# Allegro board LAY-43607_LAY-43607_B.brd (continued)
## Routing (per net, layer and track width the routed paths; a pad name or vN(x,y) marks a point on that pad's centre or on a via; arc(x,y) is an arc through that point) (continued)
D1_MECC0: length 49
  TOP w0.137: v3(67.03,35.8) 67.02,35.8 U14.M26 ; U565.G2 v2(67.08,13.71)
  L4_INT_2 w0.107: v3(67.03,35.8) 67.03,35.54 66.6,35.11 66.6,34.61 66.7,34.51 67.19,34.51 67.32,34.38 67.32,34.21 67.19,34.08 66.7,34.08 66.6,33.97 66.6,32.64 70.04,29.2 70.04,26.28 71.98,24.35 73.4,24.35 73.72,24.03 73.72,23.51 73.55,23.34 72.52,23.34 72.37,23.19 72.37,23.02 72.48,22.92 73.55,22.92 73.68,22.79 73.68,22.62 73.55,22.49 72.53,22.49 72.37,22.33 72.37,22.16 72.48,22.06 73.55,22.06 73.67,21.93 73.67,21.75 73.55,21.63 72.52,21.63 72.37,21.48 72.37,21.31 72.48,21.2 73.55,21.2 73.65,21.1 73.65,20.94 73.55,20.84 72.5,20.84 72.35,20.69 72.35,20.52 72.45,20.41 73.48,20.41 73.72,20.18 73.72,19.94 73.61,19.84 72.9,19.84 72.79,19.73 72.79,19.52 72.9,19.41 73.61,19.41 73.72,19.3 73.72,18.87 73.93,18.66 73.93,14.92 73.82,14.82 73.48,14.82 73.38,14.71 73.38,14.5 73.48,14.39 73.82,14.39 73.93,14.28 73.93,12.74 73.67,12.48 73.37,12.48 73.1,12.75 73.1,13.11 72.92,13.29 71.59,13.29 70.91,13.98 67.35,13.98 v2(67.08,13.71)
D1_MECC1: length 49.1
  TOP w0.137: U14.N25 66.22,36.6 v3(66.23,36.6) ; U565.F7 v2(71.88,14.51)
  L4_INT_2 w0.107: v3(66.23,36.6) 66.55,36.6 66.66,36.49 66.66,35.58 66.18,35.1 66.18,32.47 69.63,29.03 69.63,28.63 69.52,28.52 69.34,28.52 69.23,28.42 69.23,28.2 69.34,28.1 69.52,28.1 69.63,27.99 69.63,27.78 69.52,27.67 69.36,27.67 69.26,27.56 69.26,27.35 69.36,27.24 69.52,27.24 69.63,27.14 69.63,26.92 69.52,26.82 69.36,26.82 69.26,26.71 69.26,26.5 69.36,26.39 69.52,26.39 69.63,26.28 69.63,26.09 69.63,25.88 69.99,25.52 69.99,25.37 69.5,24.88 69.5,24.61 69.59,24.52 69.74,24.52 70.39,25.17 70.54,25.17 70.69,25.02 70.69,24.87 70.05,24.23 70.05,24.08 70.2,23.93 70.35,23.93 71,24.57 71.14,24.57 71.28,24.43 71.28,24.28 70.73,23.74 70.73,23.59 70.89,23.44 71.04,23.44 71.57,23.97 71.74,23.97 72.08,23.63 72.08,23.48 71.71,23.11 70.89,23.11 70.78,23 70.78,22.81 70.89,22.71 71.79,22.71 71.92,22.58 71.92,22.39 71.81,22.28 70.89,22.28 70.78,22.17 70.78,21.96 70.89,21.85 71.79,21.85 71.92,21.72 71.92,21.53 71.81,21.43 70.89,21.43 70.78,21.32 70.78,21.11 70.89,21 71.79,21 71.92,20.87 71.92,20.67 71.81,20.56 70.89,20.56 70.78,20.46 70.78,20.24 70.89,20.14 71.8,20.14 71.92,20.02 71.92,19.81 73.1,18.63 73.1,18.11 72.99,18 71.69,18 71.58,17.89 71.58,17.68 71.69,17.57 72.97,17.57 73.1,17.44 73.1,17.25 72.99,17.15 71.69,17.15 71.58,17.04 71.58,16.83 71.69,16.72 72.97,16.72 73.1,16.59 73.1,14.35 72.84,14.09 72.3,14.09 v2(71.88,14.51)
D1_MECC2: length 49.1
  TOP w0.137: v3(63.03,36.59) 63.03,36.6 U14.T25 ; v2(68.97,12.08) 68.54,12.51 U565.H3
  L4_INT_2 w0.107: v2(68.97,12.08) 68.97,12.34 68.76,12.55 68.06,12.55 67.95,12.45 67.95,12.04 67.84,11.94 67.63,11.94 67.52,12.04 67.52,12.25 67.42,12.35 67.2,12.35 67.1,12.25 67.1,12.04 66.99,11.94 66.78,11.94 66.67,12.04 66.67,12.42 66.56,12.52 65.9,12.52 65.51,12.13 65.17,12.13 64.93,12.37 64.93,12.53 65.12,12.72 65.51,12.72 65.72,12.93 65.72,13.28 65.61,13.39 65.28,13.39 65.13,13.54 65.13,13.78 65.24,13.89 65.43,13.89 65.55,14.01 65.55,14.69 65.45,14.8 65.02,14.8 64.91,14.91 64.91,15.12 65.02,15.23 65.45,15.23 65.55,15.33 65.55,15.57 65.4,15.72 65.16,15.72 64.97,15.92 64.97,16.75 65.08,16.85 65.57,16.85 65.68,16.96 65.68,17.17 65.57,17.28 65.02,17.28 64.91,17.39 64.91,17.62 65,17.71 65.57,17.71 65.68,17.81 65.68,18.03 65.57,18.13 65.08,18.13 64.97,18.24 64.97,18.62 64.76,18.83 64.76,18.98 65.17,19.39 65.17,19.54 65.01,19.69 64.86,19.69 64.45,19.28 64.3,19.28 64.14,19.45 64.14,24.77 63.96,24.96 63.96,25.11 64.34,25.49 64.34,25.77 64.22,25.89 64.01,25.89 63.59,25.47 63.44,25.47 63.33,25.58 63.33,25.73 63.79,26.18 63.79,26.33 63.64,26.49 63.4,26.49 62.99,26.07 62.84,26.07 62.36,26.55 62.36,27.03 62.46,27.14 63.05,27.14 63.15,27.25 63.15,27.46 63.05,27.57 62.5,27.57 62.36,27.7 62.36,27.89 62.46,27.99 63.05,27.99 63.15,28.1 63.15,28.31 63.05,28.42 62.5,28.42 62.36,28.56 62.36,28.74 62.46,28.85 63.05,28.85 63.15,28.95 63.15,29.17 63.05,29.27 62.5,29.27 62.36,29.41 62.36,30.8 62.48,30.92 62.86,30.92 62.97,31.02 62.97,31.24 62.86,31.34 62.46,31.34 62.36,31.45 62.36,31.65 62.48,31.77 62.76,31.77 62.86,31.88 62.86,32.08 62.76,32.18 62.46,32.18 62.36,32.29 62.36,33.02 62.7,33.36 62.7,33.88 62.52,34.06 62.19,34.06 62.08,34.16 62.08,34.38 62.19,34.48 62.52,34.48 62.63,34.59 62.63,36.2 v3(63.03,36.59)
D1_MECC3: length 49
  TOP w0.137: U565.H7 v2(71.88,12.91) ; v3(63.03,37.39) 63.03,37.4 U14.T24
  L4_INT_2 w0.107: v3(63.03,37.39) 62.63,37 61.92,37 61.81,36.89 61.81,32.78 61.95,32.64 61.95,26.29 63.7,24.53 63.7,24.38 63.71,24.38 63.71,18.75 63.81,18.65 64.36,18.65 64.55,18.46 64.55,18.33 64.44,18.22 63.81,18.22 63.71,18.11 63.71,17.9 63.81,17.79 64.43,17.79 64.5,17.72 64.5,17.42 64.44,17.37 63.81,17.37 63.71,17.26 63.71,17.05 63.81,16.94 64.43,16.94 64.55,16.82 64.55,16.62 64.44,16.51 63.81,16.51 63.71,16.41 63.71,16.12 63.81,16.01 64.39,16.01 64.5,15.9 64.5,14.52 64.24,14.26 64.24,13.12 62.85,11.73 62.85,11.58 63.05,11.37 63.16,11.37 63.78,11.99 63.79,11.99 64.16,12.36 64.36,12.36 65,11.72 66.07,11.72 66.16,11.63 69.46,11.63 69.57,11.74 69.57,12.79 69.68,12.9 69.97,12.9 70.07,12.79 70.07,11.78 70.23,11.63 70.47,11.63 70.58,11.74 70.58,12.04 70.68,12.15 70.9,12.15 71,12.04 71,11.87 71.11,11.77 71.74,11.77 72.03,12.06 72.5,12.06 72.64,12.2 72.64,12.35 72.09,12.91 v2(71.88,12.91)
D1_MECC4: length 49.1
  TOP w0.137: U14.M25 67.02,36.6 v3(67.03,36.6) ; U565.H2 67.08,12.11 66.12,12.11 66.04,12.03 65.44,12.03 65.3,12.16 65.3,13.48 65.12,13.66 64.52,13.66 64.38,13.53 64.38,12.57 64.25,12.43 64.05,12.43 v2(63.29,13.19)
  L4_INT_2 w0.107: v2(63.29,13.19) 63.29,12.77 63.05,12.53 62.9,12.53 62.79,12.64 62.79,13.56 62.9,13.66 63.71,13.66 63.83,13.78 63.83,14.01 63.71,14.13 62.86,14.13 62.7,14.29 62.7,14.45 62.81,14.56 63.59,14.56 63.73,14.69 63.73,14.84 63.59,14.98 62.86,14.98 62.7,15.14 62.7,15.31 62.85,15.46 63.19,15.46 63.29,15.57 63.29,24.21 63.29,24.21 63.29,24.36 61.53,26.12 61.53,32.47 61.38,32.62 61.38,33.97 61.27,34.08 60.61,34.08 60.51,34.19 60.51,34.4 60.61,34.51 61.27,34.51 61.38,34.61 61.38,35.22 61.03,35.57 61.03,37.55 61.27,37.8 64.47,37.8 64.58,37.69 64.58,36.83 64.69,36.72 64.9,36.72 65.01,36.83 65.01,37.69 65.11,37.8 65.59,37.8 65.83,37.56 65.83,37.26 66.09,37 66.92,37 67.03,36.89 v3(67.03,36.6)
D1_MECC5: length 49.1
  TOP w0.137: v3(66.23,37.4) 65.83,37.8 U14.N24 ; U565.H8 v2(72.68,12.91)
  L4_INT_2 w0.107: v3(66.23,37.4) 66.23,37.47 65.81,37.89 65.81,38.36 66.04,38.59 67.17,38.59 67.44,38.32 67.44,35.64 67.63,35.45 67.63,33.87 67.52,33.76 67.05,33.76 66.94,33.66 66.94,33.44 67.05,33.34 67.52,33.34 67.63,33.23 67.63,32.25 67.68,32.21 67.68,32.2 70.55,29.33 70.55,29.32 70.79,29.08 70.79,28.71 70.68,28.6 70.56,28.6 70.45,28.49 70.45,28.28 70.56,28.17 70.68,28.17 70.79,28.07 70.79,27.85 70.68,27.75 70.56,27.75 70.45,27.64 70.45,27.43 70.56,27.32 70.68,27.32 70.79,27.21 70.79,26.11 72.15,24.76 72.4,24.76 72.51,24.86 72.51,24.92 72.62,25.03 72.83,25.03 72.94,24.92 72.94,24.86 73.04,24.76 73.59,24.76 74.13,24.22 74.13,23.56 74.25,23.43 74.97,23.43 75.11,23.29 75.11,23.14 74.97,23.01 74.25,23.01 74.13,22.88 74.13,22.7 74.28,22.55 75.75,22.55 75.88,22.42 75.88,22.25 75.74,22.12 74.23,22.12 74.13,22.01 74.13,21.85 74.25,21.73 75.37,21.73 75.5,21.59 75.5,21.44 75.37,21.3 74.25,21.3 74.13,21.17 74.13,21 74.25,20.87 75.27,20.87 75.4,20.75 75.4,20.58 75.27,20.44 74.25,20.44 74.13,20.32 74.13,20.14 74.25,20.02 74.99,20.02 75.12,19.89 75.12,19.72 74.99,19.59 74.47,19.59 74.36,19.48 74.36,12.5 74.05,12.18 73.12,12.18 72.68,12.63 v2(72.68,12.91)
D1_MECC6: length 49
  TOP w0.137: v3(63.82,36.59) 63.82,36.6 U14.R25 ; U565.J3 68.33,11.66 69.15,11.66 69.41,11.91 69.41,12.3 70.9,13.78 70.9,14.7 70.42,15.17 70.42,15.77 70.28,15.91 70.09,15.91 69.95,15.77 69.95,15.09 70.44,14.6 70.44,13.78 69.83,13.17 v2(69.41,13.17)
  L4_INT_2 w0.107: v3(63.82,36.59) 63.82,36.92 63.72,37.03 63.52,37.03 63.38,36.89 63.38,35.98 63.41,35.96 63.41,35.64 63.06,35.29 63.06,35.1 63.17,34.99 63.94,34.99 64.05,34.89 64.05,34.67 63.94,34.57 63.21,34.57 63.1,34.46 63.1,34.25 63.21,34.14 63.81,34.14 63.95,33.99 63.95,33.84 63.79,33.68 63.17,33.68 63.06,33.56 63.06,32.46 63.38,32.14 63.38,30.85 63.23,30.71 63.23,29.83 63.56,29.5 63.56,27.14 64.94,25.77 64.94,24.77 64.55,24.38 64.55,24.2 64.66,24.09 65.15,24.09 65.26,23.98 65.26,23.77 65.15,23.66 64.66,23.66 64.55,23.56 64.55,23.34 64.66,23.24 65.15,23.24 65.26,23.13 65.26,22.92 65.15,22.81 64.66,22.81 64.55,22.7 64.55,22.49 64.66,22.38 65.15,22.38 65.26,22.28 65.26,22.06 65.15,21.96 64.66,21.96 64.55,21.85 64.55,21.64 64.66,21.53 65.15,21.53 65.26,21.42 65.26,21.21 65.15,21.1 64.66,21.1 64.55,21 64.55,20.51 64.95,20.1 65.29,20.1 66,19.39 66,18.89 65.9,18.78 65.9,13.52 66.12,13.29 66.44,13.29 66.76,12.97 67.71,12.97 67.82,13.08 67.82,13.2 67.95,13.33 68.14,13.33 68.25,13.22 68.25,13 68.35,12.9 69.14,12.9 v2(69.41,13.17)
D1_MECC7: length 49
  TOP w0.137: U565.J7 v2(70.65,12.53) ; v3(63.82,37.39) 63.82,37.4 U14.R24
  L4_INT_2 w0.107: v2(70.65,12.53) 71.15,12.53 71.47,12.21 71.83,12.21 71.91,12.29 71.91,12.44 71.82,12.52 71.72,12.52 71.5,12.75 71.5,12.85 71.28,13.07 71.2,13.07 70.69,13.58 67.73,13.58 67.47,13.32 66.92,13.32 66.66,13.58 66.66,15.08 66.77,15.19 67.13,15.19 67.24,15.3 67.24,15.51 67.13,15.62 66.77,15.62 66.66,15.72 66.66,16.68 66.77,16.78 67.34,16.78 67.44,16.89 67.44,17.1 67.34,17.21 66.78,17.21 66.66,17.32 66.66,19.51 65.67,20.5 65.67,26.21 65.55,26.33 64.95,26.33 64.82,26.47 64.82,26.61 64.92,26.72 65.54,26.72 65.62,26.79 65.62,27 65.48,27.14 64.15,27.14 64.02,27.27 64.02,27.46 64.12,27.57 65.51,27.57 65.62,27.67 65.62,27.88 65.51,27.98 64.08,27.98 63.98,28.09 63.98,28.3 64.08,28.41 65.51,28.41 65.62,28.52 65.62,28.83 65.09,29.35 64.83,29.35 64.29,28.81 64.14,28.81 63.98,28.96 63.98,29.11 64.55,29.68 64.55,30.13 64.44,30.23 63.75,30.23 63.65,30.34 63.65,30.53 63.77,30.66 64.24,30.66 64.39,30.82 64.39,31.05 64.24,31.2 63.9,31.2 63.8,31.3 63.8,31.52 63.9,31.62 64.24,31.62 64.35,31.73 64.35,32.05 64.05,32.34 64.05,32.61 63.91,32.75 63.58,32.75 63.47,32.86 63.47,33.06 63.59,33.18 63.95,33.18 64.05,33.28 64.05,33.48 64.19,33.62 64.2,33.62 64.3,33.73 64.3,37.29 64.2,37.39 v3(63.82,37.39)
D1_MODT0: length 142.7
  TOP w0.137: v1(79.76,10.91) 79.36,11.31 78,11.31 77.38,10.7 77.19,10.7 77.04,10.85 76.44,10.85 76.18,11.11 76.18,11.96 76.04,12.1 75.42,12.1 75.3,11.98 75.3,11.33 75.18,11.21 75.01,11.21 74.89,11.33 74.89,11.98 74.77,12.1 74.6,12.1 74.48,11.98 74.48,11.33 74.36,11.21 74.19,11.21 74.07,11.33 74.07,11.98 73.95,12.1 73.68,12.1 73.54,11.96 73.54,11.44 73.41,11.31 70.48,11.31 70.35,11.44 70.35,12.01 70.21,12.14 69.93,12.14 69.8,12.01 69.8,11.44 69.66,11.31 68.68,11.31 v1(68.28,10.91) ; v2(90.08,20.85) 90.1,20.83 94.68,20.83 94.82,20.97 94.82,21.19 94.68,21.33 65.01,21.33 56.38,29.95 56.38,33.58 57.02,34.22 U14.AD28 ; v1(45.32,10.91) 44.92,11.31 44.92,11.9 44.72,12.11 44.31,12.11 44.12,12.29 44.12,12.75 43.96,12.91 43.47,12.91 43.34,13.05 43.34,13.13 43.32,13.14 43.32,14.74 42.92,15.14 42.92,15.57 42.81,15.68 42.46,15.68 42.21,15.93 42.21,16.51 41,17.72 R135.1
  L3_INT_1 w0.107: v1(45.32,10.91) 45.32,13.84 46.14,14.66 47.71,14.66 47.91,14.86 48.74,14.86 48.76,14.89 49.08,14.89 49.11,14.86 49.54,14.86 49.56,14.89 49.88,14.89 49.91,14.86 51.49,14.86 52.82,13.53 53.41,13.53 53.65,13.29 56.6,13.29 56.8,13.09 v1(56.8,10.91) 57.07,10.91 57.4,11.24 57.4,11.91 58.01,12.52 58.36,12.52 58.78,12.94 58.78,14.54 59.13,14.89 63.68,14.89 63.84,14.74 65.44,14.74 65.9,14.28 65.9,13.55 66.12,13.32 67.75,13.32 68.28,12.8 v1(68.28,10.91) ; v2(90.08,20.85) 89.64,20.41 89.64,14.29 90.44,13.49 90.44,12.5 90.41,12.46 90.41,11.74 91.24,10.91 v1(91.24,10.91)
  L4_INT_2 w0.107: v1(91.24,10.91) 91.24,11.29 90.81,11.72 90.68,11.72 90.3,12.11 89.53,12.11 89.43,12.21 89.43,12.42 89.32,12.52 89.11,12.52 89,12.42 89,12.21 88.89,12.11 88.32,12.11 88.32,12.11 85.57,12.11 85.43,12.25 83.26,12.25 82.32,11.31 81.4,11.31 81.29,11.2 81.29,10.85 81.19,10.75 80.97,10.75 80.87,10.85 80.87,11.42 80.69,11.6 79.55,11.6 79.38,11.42 79.38,11.1 79.56,10.91 v1(79.76,10.91)
D1_MRAS_B: length 139.7
  TOP w0.137: v1(83.76,10.11) 83.76,10.28 84.16,10.68 84.16,11.07 84.4,11.31 84.73,11.31 84.96,11.54 84.96,12.29 85.23,12.57 85.58,12.57 85.71,12.7 85.71,13.57 85.85,13.71 86.13,13.71 86.26,13.57 86.26,12.7 86.4,12.57 88.81,12.57 89.24,12.14 89.24,11.54 89.48,11.31 92.05,11.31 92.19,11.45 92.19,11.5 92.33,11.64 92.6,11.64 92.74,11.5 92.74,11.45 92.88,11.31 95.51,11.31 95.64,11.17 95.64,10.51 v1(95.24,10.11) ; R127.1 45.81,5.35 45.81,9.81 45.92,9.92 46.38,9.92 46.57,10.12 46.57,10.57 46.8,10.8 48.07,10.8 48.36,10.51 48.92,10.51 v1(49.32,10.11) ; U14.AA28 59.42,33.81 59.34,33.73 59.34,29.5 65.74,23.1 84.05,23.1 84.59,23.64 94.98,23.64 96.52,22.1 v2(96.52,21.25)
  L3_INT_1 w0.107: v1(95.24,10.11) 95.62,10.49 95.62,11.07 95.88,11.32 96.26,11.32 97.08,12.15 97.08,14.18 97.24,14.33 97.72,14.33 97.88,14.49 97.88,14.71 97.72,14.87 97.24,14.87 97.08,15.02 97.08,16.24 97.24,16.4 97.62,16.4 97.77,16.55 97.77,16.77 97.62,16.93 97.24,16.93 97.08,17.09 97.08,17.31 97.24,17.46 97.62,17.46 97.77,17.62 97.77,17.84 97.62,18 97.24,18 97.08,18.15 97.08,18.47 95.99,19.56 95.99,20.72 v2(96.52,21.25) ; v1(60.8,10.11) 60.38,10.52 59.84,10.52 59.83,10.53 57.95,10.53 57.11,9.69 55.04,9.69 54.69,9.34 52.69,9.34 52.39,9.64 52.39,12.34 52.22,12.5 49.23,12.5 48.93,12.2 48.93,10.5 v1(49.32,10.11)
  BOTTOM w0.137: v1(83.76,10.11) 83.49,9.84 82.63,9.84 82.46,9.67 82.18,9.67 81.91,9.94 81.91,10.72 81.14,11.48 78.12,11.48 77.79,11.16 77.79,11.1 77.76,11.07 77.76,10.23 77.42,9.89 75.16,9.89 75.02,10.02 75.02,10.26 74.88,10.39 74.61,10.39 74.47,10.26 74.47,10.02 74.34,9.89 73.88,9.89 73.35,10.42 73.34,10.42 73.25,10.51 72.68,10.51 v1(72.28,10.11) 71.72,10.11 71.3,9.69 70.21,9.69 70.07,9.83 70.07,10.35 69.93,10.48 69.66,10.48 69.52,10.35 69.52,9.83 69.38,9.69 68.46,9.69 68.45,9.71 66.46,9.71 65.82,10.34 63.22,10.34 62.98,10.11 62.98,9.3 62.59,8.91 61.34,8.91 61.2,9.04 61.2,9.71 v1(60.8,10.11)
D1_MWE_B: length 134.2
  TOP w0.137: U14.AB28 58.62,34.22 58.41,34.01 58.41,33.03 58.57,32.87 58.74,32.87 58.9,32.71 58.9,32.48 58.74,32.32 58.57,32.32 58.41,32.16 58.41,31.93 58.57,31.77 58.74,31.77 58.9,31.61 58.9,31.39 58.74,31.22 58.57,31.22 58.41,31.06 58.41,29.8 65.56,22.65 85.18,22.65 v2(85.35,22.83) ; v1(44.52,10.11) 44.34,10.11 43.94,10.51 43.54,10.51 42,12.06 42,14.27 41.78,14.49 41.61,14.49 41.38,14.26 41.21,14.26 41.09,14.38 41.09,14.55 41.22,14.68 41.22,14.88 41.09,15.01 R126.1
  L3_INT_1 w0.107: v1(90.44,10.11) 90.29,10.11 89.89,10.51 89.52,10.51 89.5,10.52 89.48,10.52 88.99,11.02 88.99,11.51 89.04,11.57 89.04,11.97 88.48,12.53 88.48,12.95 87.91,13.52 87.45,13.52 87.16,13.81 87.16,19.74 83.26,23.64 83.26,24.01 81.1,26.16 81.1,26.31 81.41,26.62 81.56,26.62 v2(85.35,22.83)
  L4_INT_2 w0.107: v1(44.52,10.11) 44.94,9.69 46.71,9.69 46.87,9.54 46.87,9.16 47.26,8.77 47.26,8.53 47.37,8.43 47.74,8.43 47.83,8.51 47.83,9.16 48.36,9.69 50.28,9.69 50.77,9.2 50.77,8.71 50.94,8.55 51.68,8.55 51.89,8.75 51.89,9.36 52.69,10.16 54.71,10.16 55.04,10.49 55.36,10.49 55.58,10.27 55.58,10.06 55.69,9.95 55.84,9.95 v1(56,10.11) 56.16,10.11 56.58,9.69 57.38,9.69 57.9,9.17 57.9,8.14 58.04,8 58.67,8 58.79,8.11 58.79,9.44 59.84,10.49 62.5,10.49 63.24,9.75 63.88,9.75 64.3,10.18 65.75,10.18 66.07,10.49 67.1,10.49 v1(67.48,10.11) 67.86,10.49 68.44,10.49 68.58,10.36 70.56,10.36 70.69,10.49 72.12,10.49 72.12,10.49 72.44,10.49 72.44,10.49 72.7,10.23 72.7,9.95 72.92,9.72 73.24,9.72 73.32,9.81 73.72,9.81 73.83,9.91 73.83,10.54 73.94,10.64 74.15,10.64 74.26,10.54 74.26,9.91 74.36,9.81 74.58,9.81 74.68,9.91 74.68,10.54 74.79,10.64 75,10.64 75.11,10.54 75.11,9.91 75.22,9.81 77.32,9.81 78,10.49 78.58,10.49 v1(78.96,10.11)
  BOTTOM w0.137: v1(90.44,10.11) 90.16,10.11 90.03,9.97 90.03,9.85 89.89,9.71 89.1,9.71 88.75,10.06 88.58,10.06 88.53,10.11 87.05,10.11 87.01,10.06 86.04,10.06 84.88,8.91 82.8,8.91 82.39,9.32 81.11,9.32 80.74,9.69 80.74,9.89 81.37,10.51 81.37,10.71 81.17,10.9 80.98,10.9 80.35,10.28 80.16,10.28 79.93,10.51 79.36,10.51 v1(78.96,10.11)
D1_PAROUT: length 135.9
  TOP w0.137: U565.T3 68.28,6.11 v2(68.69,5.69) ; v2(72.81,25.44) 71.66,25.44 71.66,25.45 66.51,25.45 62.2,29.76 62.2,32.87 62.73,33.41 62.73,33.69 U14.V28 ; U17.T3 57.01,5.71 57.01,5.66 57.08,5.59 v2(57.08,5.53) ; R134.1 40.13,5.57 40.34,5.36 40.34,5.16 40.1,4.92 40.1,4.72 40.29,4.53 40.49,4.53 40.73,4.77 40.93,4.77 41.31,4.39 42.35,4.39 42.48,4.53 44.09,4.53 44.1,4.54 44.3,4.54 45.32,5.56 v1(45.32,6.11) ; v2(80.17,5.69) 80.17,5.7 U16.T3
  L3_INT_1 w0.107: v2(72.81,25.44) 71.84,25.44 71.73,25.55 71.73,26.37 71.63,26.48 69.55,26.48 69.44,26.37 69.44,20.77 70.07,20.15 79.38,20.15 81.17,18.35 81.17,17.91 80.87,17.61 80.87,16.93 80.33,16.4 80.33,15.49 80.85,14.97 80.85,14.36 80.43,13.93 80.43,12.81 81.44,11.79 81.44,8.68 82.8,7.32 83.12,7.32 83.18,7.38 85.13,7.38 86.05,6.45 86.67,6.45 87.73,5.39 89.24,5.39 89.95,6.11 v1(91.24,6.11) ; v2(80.17,5.69) 81.16,5.69 81.27,5.58 81.27,3.72 81.16,3.62 71.9,3.62 71.56,3.96 70.42,3.96 v2(68.69,5.69) 68.69,5.2 68.94,4.96 68.94,4.29 68.78,4.13 68.36,4.13 68.2,4.29 68.2,4.84 67.64,5.41 67.33,5.41 67.33,5.41 67.01,5.41 67.01,5.41 66.77,5.41 65.05,3.68 57.87,3.68 57.08,4.47 v2(57.08,5.53)
  L4_INT_2 w0.107: v1(45.32,6.11) 45.32,4.56 45.92,3.96 54.99,3.96 55.81,4.78 55.81,5.71 56.07,5.97 56.64,5.97 v2(57.08,5.53)
  BOTTOM w0.137: v2(80.17,5.69) 80.23,5.69 82.26,3.66 90.74,3.66 91.97,4.89 91.97,5.38 v1(91.24,6.11)
DDR4_CLK_TERM: length 1.7
  BOTTOM w0.137: C431.2 44.57,3.7 R138.2 46.21,3.7 R137.2
DDR4_ZQ0: length 2.4
  TOP w0.137: R105.1 61.65,14.15 U17.F9
DDR4_ZQ1: length 2.2
  TOP w0.137: U18.F9 50.17,14.15 51.75,14.15 51.79,14.11 R106.1
DDR4_ZQ2: length 2.1
  TOP w0.137: U15.F9 96.45,14.11 96.46,14.11 97.57,14.11 R103.1
DDR4_ZQ3: length 2.2
  TOP w0.137: U16.F9 84.61,14.15 R104.1
DDR4_ZQ5: length 2.3
  TOP w0.137: U565.F9 R107.1
DDR_CLK_100MHZ_LVCMOS: length 85.6
  TOP w0.137: R782.2 33.5,67.36 34.5,68.36 35.06,68.36 38.14,65.28 38.14,64.4 38.8,63.73 38.8,58.95 v2(37.34,57.48) ; v3(68.62,40.6) U14.J20
  L3_INT_1 w0.107: v2(37.34,57.48) 40.37,54.45 40.37,42.43 39.61,41.67 39.65,41.63 39.65,37.85 39.38,37.58 39.38,34.82 40.33,33.88 40.33,31.78 44.16,27.96 66.58,27.96 68.21,29.58 68.21,40.18 v3(68.62,40.6)
DDR_VREF1: length 3.5
  BOTTOM w0.254: v1(89.64,9.31) 89.08,9.31 C1406.1
  BOTTOM w0.381: R960.2 87.26,8.55 R961.1 C1406.1
DDR_VREF2: length 2.9
  BOTTOM w0.254: C1430.1 78.14,9.29 v1(78.16,9.31)
  BOTTOM w0.381: R963.1 76.14,9.28 R962.2 76.99,9.28 C1430.1
DDR_VREF3: length 3.4
  BOTTOM w0.254: R954.2 R955.1 C669.1 54.84,9.67 v1(55.2,9.31)
DDR_VREF4: length 2.7
  BOTTOM w0.254: v1(43.72,9.31) 43.7,9.29 C1382.1
  BOTTOM w0.381: R956.2 41.87,9.28 R957.1 C1382.1
DDR_VREF5: length 3
  BOTTOM w0.254: v1(66.68,9.31) 66.22,9.31 66.2,9.29 C1577.1
  BOTTOM w0.381: R959.1 64.62,9.28 R958.2 65.54,9.28 C1577.1
DDR_VTT: length 2
  TOP w0.254: v4(76.06,73.75) 75.7,74.11 75.7,74.55 75.48,74.76 U561.30
  vias: v2(37.12,19.52) v2(37.12,18.86) v2(37.81,19.52) v2(37.81,18.86) v2(38.44,19.52) v2(38.44,18.89) v2(39.08,19.52) v2(39.1,18.89) v4(81.49,76.22) v4(81.52,75.51) v4(82.41,76.6) v4(82.41,75.89) v4(82.41,75.18) v4(82.41,74.47)
DIFF_SYSCLK_N: length 56.4
  TOP w0.124: U14.AB13 v1(58.22,47) ; U50.16 23.6,64.84 23.51,64.75 19.72,64.75 18.99,64.02 18.99,60.55 20.5,59.04 22.17,59.04 23.04,59.91 23.5,59.91 v2(23.62,59.8)
  BOTTOM w0.124: v1(58.22,47) 58.21,47.01 57.7,47.01 56.76,46.08 52.14,46.08 51.56,46.66 49.89,46.66 47.59,48.97 44.22,48.97 32.68,60.51 29.44,60.51 28.94,60.01 23.83,60.01 v2(23.62,59.8)
DIFF_SYSCLK_P: length 56.4
  TOP w0.124: v2(23.62,60.54) 23.31,60.23 22.9,60.23 22.04,59.36 20.63,59.36 19.31,60.69 19.31,63.89 19.85,64.43 23.51,64.43 23.6,64.34 U50.17
  TOP w0.137: U14.AA13 v1(59.03,46.99)
  BOTTOM w0.124: v1(59.03,47) 58.63,47.39 57.62,47.39 56.63,46.4 52.28,46.4 51.69,46.98 50.02,46.98 47.72,49.29 44.36,49.29 32.81,60.83 29.31,60.83 28.8,60.33 23.83,60.33 v2(23.62,60.54)
EMI2_MDC: length 29
  TOP w0.137: R870.2 47.19,58.31 47.08,58.21 v2(46.7,58.21) ; U123.C11 37.42,69.94 v2(36.85,69.37)
  BOTTOM w0.137: v2(36.85,69.37) 37.28,69.37 37.56,69.65 44.47,69.65 45.25,68.87 45.25,66.96 44.71,66.42 44.71,66.37 41.92,63.58 41.92,61.62 45.34,58.21 v2(46.7,58.21) 47.63,58.21 47.73,58.31 R870.2
EMI2_MDIO: length 37.9
  TOP w0.137: R871.1 49.77,59.33 49.91,59.19 v2(49.91,58.64) 53.56,54.98 53.56,54.86 U14.AH3 ; U123.D10 37.86,72.27 37.86,69.34 v2(37.22,68.7)
  BOTTOM w0.137: v2(37.22,68.7) 37.91,69.39 44.36,69.39 44.86,68.89 44.86,66.94 41.66,63.74 41.66,61.51 45.39,57.78 49.05,57.78 v2(49.91,58.64)
FA_VL: length 3.9
  TOP w0.137: U14.U5 v1(62.22,53.39)
  TOP w0.381: U14.AB21 v1(59.02,40.6)
  L3_INT_1 w0.488: J12.2 41.57,38.16 ; J12.2 41.57,36.74 ; J12.2 42.28,37.45
  BOTTOM w0.508: R102.1 v4(45.83,36.56)
FTM7_CH0: length 104.4
  TOP w0.137: U14.A19 76.87,41.8 77.24,42.17 82.65,42.17 84.24,40.58 85.56,40.58 85.87,40.89 91.52,40.89 v2(91.83,40.58) ; v2(86.17,113.1) 86.64,112.63 U548.5
  L3_INT_1 w0.107: v2(88.53,102.67) 88.53,94.91 87.11,93.49 87.11,90.21 86.29,89.4 86.29,84.57 87.34,83.52 89.06,83.52 94.76,77.82 v2(95.77,77.82)
  L4_INT_2 w0.107: v2(91.83,40.58) 91.33,41.08 91.33,43.61 92.96,45.23 92.96,55.02 92.45,55.53 92.45,57.65 92.38,57.72 92.38,58.41 92.65,58.69 92.65,60.37 91,62.02 91,65.08 94.13,68.21 94.13,76.18 v2(95.77,77.82)
  BOTTOM w0.137: v2(86.17,113.1) 86.67,113.6 88.45,113.6 88.85,113.2 88.85,106.11 88.53,105.79 v2(88.53,102.67)
FUSE_PWR_STATUS#: length 59.9
  TOP w0.137: v2(94.85,63.94) 94.22,64.57 94.22,65.3 94.11,65.41 U566.4
  L3_INT_1 w0.107: v2(94.85,63.94) 95.53,63.26 97.5,63.26 97.63,63.39 98.35,63.39 99.14,62.6 104.13,62.6 104.98,61.75 108.78,61.75 v2(108.94,61.59)
  L4_INT_2 w0.107: v2(113.16,100.3) 113.7,99.76 113.7,82.54 110.73,79.57 110.73,63.15 109.17,61.59 v2(108.94,61.59)
  BOTTOM w0.137: R948.2 113.98,100.3 v2(113.16,100.3)
GPIO3_02: length 93.2
  TOP w0.137: J67.6 19.49,106.7 19.1,106.31 19.1,106.29 18.81,106.01 v2(18.39,106.01) ; v2(59.82,55) U14.Y3
  L3_INT_1 w0.107: v2(58.27,61.54) 57.62,62.2 54.29,62.2 53.35,61.26 46.56,61.26 46.23,61.59 45.05,61.59 43.11,63.52 36.23,63.52 34.99,64.77 33.61,64.77 28.36,70.02 23.32,70.02 21.92,71.41 18.55,71.41 17.5,72.46 17.5,78.71 18.05,79.26 18.05,91.24 17.5,91.79 17.5,101.23 18.21,101.94 18.21,103.74 18.89,104.41 18.89,105.55 18.71,105.72 18.68,105.72 v2(18.39,106.01)
  L4_INT_2 w0.107: v2(59.82,55) 60.21,55.38 60.21,55.95 59.82,56.34 59.82,59.99 v2(58.27,61.54)
  BOTTOM w0.137: U543.4 17.95,107.67 18.44,107.18 18.44,106.49 18.39,106.43 v2(18.39,106.01)
GPIO3_03: length 95.4
  TOP w0.137: J67.10 20.03,102.62 v2(20.03,103.2) ; v2(59.82,54.2) U14.Y4
  L3_INT_1 w0.107: v2(60.36,61.32) 60.36,61.95 55.87,66.44 35.77,66.44 34.5,65.16 33.54,65.16 28.38,70.32 23.34,70.32 22.02,71.64 18.65,71.64 17.73,72.56 17.73,78.55 18.7,79.51 18.7,96.88 19.41,97.59 19.41,102.58 v2(20.03,103.2)
  L4_INT_2 w0.107: v2(60.36,61.32) 60.08,61.03 60.08,59.62 60.43,59.27 60.43,54.8 v2(59.82,54.2)
  BOTTOM w0.137: v2(20.03,103.2) 19.26,102.43 19.26,100.29 17.99,99.01 U544.1
GPIO3_04: length 99.9
  TOP w0.137: v2(59.02,55) U14.AA3 ; v2(18.33,111.01) 18.83,111.01 19.49,110.35 J67.4
  L3_INT_1 w0.107: v2(18.33,111.01) 17.5,110.17 17.5,107.8 17.98,107.32 17.98,102.04 17.27,101.33 17.27,91.69 17.82,91.14 17.82,79.36 17.27,78.81 17.27,72.3 18.39,71.18 21.71,71.18 23.37,69.52 27.76,69.52 28.26,69.01 28.26,68.31 29.99,66.58 31.1,66.58 33.15,64.53 34.89,64.53 36.19,63.24 43.01,63.24 44.89,61.35 46.13,61.35 46.46,61.02 53.64,61.02 53.94,61.32 55.98,61.32 56.07,61.23 57.16,61.23 v2(57.55,61.61)
  L4_INT_2 w0.107: v2(59.02,55) 59.41,55.38 59.41,59.75 v2(57.55,61.61)
  BOTTOM w0.137: v2(18.33,111.01) 18.64,110.7 18.64,108.54 18.27,108.17 U543.3
GPIO3_05: length 92.4
  TOP w0.137: v2(14.54,105.83) J67.5 ; v2(58.22,55) U14.AB3
  L3_INT_1 w0.107: v2(53.74,59.12) 53.08,59.12 52.81,58.85 50.99,58.85 50.08,59.76 47.25,59.76 47.23,59.74 43.03,59.74 41.77,61 37.1,61 34.5,63.6 32.73,63.6 30.71,65.61 29.62,65.61 27.8,67.43 20.6,67.43 16.33,71.7 16.33,79.31 16.86,79.84 16.86,90.77 16.33,91.3 16.33,101.71 17.05,102.43 17.05,103.56 15.06,105.54 14.82,105.54 v2(14.54,105.83)
  L4_INT_2 w0.107: v2(58.22,55) 57.84,55.38 57.84,56.15 58.08,56.39 58.08,57.93 56.89,59.12 v2(53.74,59.12)
  BOTTOM w0.137: U543.5 15.36,107.92 14.54,107.09 v2(14.54,105.83)
GPIO3_06: length 100.3
  TOP w0.137: v2(17.14,112.23) J67.2 ; v2(58.22,54.2) U14.AB4
  L3_INT_1 w0.107: v2(57.03,60.01) 56.04,61 55.97,61 55.88,61.09 54.03,61.09 53.74,60.79 46.36,60.79 46.03,61.12 42.65,61.12 42.06,61.7 37.39,61.7 34.79,64.3 33.05,64.3 31,66.35 29.89,66.35 28.03,68.21 28.03,68.86 27.7,69.19 23.37,69.19 21.61,70.94 18.29,70.94 17.03,72.2 17.03,78.9 17.58,79.45 17.58,91.04 17.03,91.59 17.03,101.42 17.75,102.14 17.75,107.22 17.14,107.83 v2(17.14,112.23)
  L4_INT_2 w0.107: v2(58.22,54.2) 58.61,54.58 58.61,58.43 v2(57.03,60.01)
  BOTTOM w0.137: v2(17.14,112.23) 17.14,111.23 18.1,110.28 18.1,109.4 17.87,109.17 U543.1
GPIO3_07: length 90.6
  TOP w0.137: v2(19.93,100.58) 19.91,100.55 19.91,99.96 J67.12 ; v2(60.62,54.2) U14.W4
  L3_INT_1 w0.107: v2(60.71,60.77) 61,61.06 61,61.75 56.08,66.67 35.68,66.67 35.21,66.21 32.86,66.21 28.48,70.59 23.44,70.59 21.77,72.26 18.51,72.26 17.98,72.79 17.98,78.16 18.95,79.13 18.95,95.65 19.93,96.63 v2(19.93,100.58)
  L4_INT_2 w0.107: v2(60.71,60.77) 60.71,54.67 60.62,54.58 v2(60.62,54.2)
  BOTTOM w0.137: U544.3 17.91,98.01 18.15,97.77 18.53,97.77 19.93,99.17 v2(19.93,100.58)
GPIO3_08: length 85.1
  TOP w0.137: J67.9 v2(14.54,100.88) ; U14.AC3 v2(57.42,55)
  L3_INT_1 w0.107: v2(14.54,100.88) 15.54,100.88 16.1,100.32 16.1,91.2 16.63,90.67 16.63,79.93 16.1,79.4 16.1,71.6 20.54,67.16 27.74,67.16 29.53,65.38 30.61,65.38 32.63,63.36 34.41,63.36 37.01,60.76 41.68,60.76 43.14,59.3 46.31,59.3 46.72,58.89 49.25,58.89 49.64,59.28 50.23,59.28 50.89,58.62 53.45,58.62 53.48,58.66 v2(54.18,58.66)
  L4_INT_2 w0.107: v2(54.18,58.66) 54.18,58.03 56.24,55.96 56.24,55.64 56.47,55.41 57.01,55.41 v2(57.42,55)
  BOTTOM w0.137: v2(14.54,100.88) 15.39,100.03 15.39,99.49 16.12,98.76 U544.7
GPIO3_09: length 73.2
  TOP w0.137: v2(55.69,69.79) 55.69,65.45 59,62.15 59,57.95 60.58,56.36 60.58,55.84 U14.W2 ; v2(20.08,90.42) 19.49,89.82 J67.20
  L3_INT_1 w0.107: v2(20.08,90.42) 19.79,90.13 19.79,79.48 22.09,77.18 26.49,77.18 31.79,71.88 33.83,71.88 35.22,70.48 35.56,70.48 36.07,71 37.6,71 37.84,70.77 39.14,70.77 39.63,71.26 43.08,71.26 43.63,70.71 51.21,70.71 51.96,69.96 55.51,69.96 v2(55.69,69.79)
  BOTTOM w0.137: v2(20.08,90.42) 18.06,92.44 U545.4
GPIO3_10: length 76.4
  TOP w0.137: v2(54.29,69.08) 54.29,62.13 U14.Y1 ; v2(20,95.5) 19.49,94.99 J67.16
  L3_INT_1 w0.107: v2(54.29,69.08) 53.43,68.22 36.57,68.22 35.13,69.67 32.8,69.67 29.21,73.26 29.21,73.54 27.03,75.73 22.88,75.73 19.21,79.39 19.21,94.72 v2(20,95.5)
  BOTTOM w0.137: U545.1 18.44,93.94 v2(20,95.5)
GPIO3_11: length 95.3
  TOP w0.137: J67.1 v2(14.54,111.01) ; U14.AA1 59.42,56.6 55.35,60.68 v2(54.36,60.68)
  L3_INT_1 w0.107: v2(14.54,111.01) 16.78,108.76 16.78,107.85 17.51,107.12 17.51,102.23 16.8,101.52 16.8,91.49 17.35,90.95 17.35,79.55 16.8,79 16.8,71.97 18.17,70.6 20.53,70.6 23.13,68 27.91,68 29.8,66.11 30.91,66.11 32.95,64.06 34.7,64.06 37.3,61.47 41.97,61.47 43.23,60.21 47.04,60.21 47.06,60.23 53.91,60.23 v2(54.36,60.68)
  BOTTOM w0.137: U543.7 16.02,108.92 14.54,110.41 v2(14.54,111.01)
GPIO3_12: length 94.9
  TOP w0.137: v2(59.02,55.79) U14.AA2 ; J67.3 v2(14.54,108.65)
  L3_INT_1 w0.107: v2(54.28,59.53) 53.16,59.53 52.72,59.09 51.08,59.09 50.17,59.99 47.16,59.99 47.13,59.97 43.13,59.97 41.87,61.23 37.2,61.23 34.6,63.83 32.82,63.83 30.78,65.88 29.69,65.88 27.81,67.76 23.04,67.76 20.6,70.2 18.24,70.2 16.57,71.88 16.57,79.21 17.1,79.74 17.1,90.87 16.57,91.4 16.57,101.62 17.28,102.33 17.28,107.03 15.65,108.65 v2(14.54,108.65)
  L4_INT_2 w0.107: v2(54.28,59.53) 55.17,60.42 57.2,60.42 59.02,58.59 v2(59.02,55.79)
  BOTTOM w0.137: U543.6 15.19,108.42 14.96,108.65 v2(14.54,108.65)
GPIO3_13: length 75
  TOP w0.137: v2(20.01,93.19) 20.01,92.43 J67.18 ; v2(56.35,69.38) 56.35,65.24 59.26,62.32 59.26,58.33 61.02,56.57 U14.W1
  L3_INT_1 w0.107: v2(20.01,93.19) 19.51,92.69 19.51,79.43 21.99,76.95 22.04,76.95 23.03,75.96 27.12,75.96 27.2,75.89 27.28,75.89 31.53,71.64 33.73,71.64 35.22,70.16 39,70.16 39.87,71.03 42.98,71.03 43.53,70.48 51.11,70.48 51.86,69.73 54.91,69.73 55.26,69.38 55.86,69.38 55.86,69.38 v2(56.35,69.38)
  BOTTOM w0.137: U545.3 18.09,92.94 18.14,92.89 19.71,92.89 v2(20.01,93.19)
GPIO3_14: length 84.3
  TOP w0.137: U14.AB1 58.62,56.6 57.34,57.89 v2(56.92,57.89) ; J67.11 v2(14.54,98.37)
  L3_INT_1 w0.107: v2(56.92,57.89) 56.36,57.33 52.93,57.33 52.91,57.35 51.4,57.35 50.93,57.81 48.51,57.81 48.26,57.56 46.25,57.56 45.5,58.31 43.01,58.31 41.56,59.76 38.82,59.76 38.54,59.48 35.22,59.48 30.46,64.24 28.06,64.24 27.6,64.71 19.35,64.71 18.9,64.26 18.29,64.26 15.8,66.74 15.8,73.78 15.71,73.88 15.71,97.25 14.87,98.08 14.82,98.08 v2(14.54,98.37)
  BOTTOM w0.137: U544.6 15.73,98.26 15.5,98.49 15.08,98.49 14.96,98.37 v2(14.54,98.37)
GPIO3_15: length 78.8
  TOP w0.137: J67.15 14.54,93.39 v2(14.54,93.39) ; v2(56.62,55) U14.AD3
  L3_INT_1 w0.107: v2(56.62,55) 56.24,55.38 56.24,55.92 55.05,57.11 51.3,57.11 50.84,57.58 48.61,57.58 47.53,56.5 46.14,56.5 44.68,57.97 42.9,57.97 41.34,59.53 38.92,59.53 38.63,59.24 35.09,59.24 31.71,62.61 30.93,62.61 30.04,63.5 26.98,63.5 26.23,64.25 19.46,64.25 19.23,64.03 18.19,64.03 15.57,66.65 15.57,73.69 14.84,74.42 14.84,79.95 15.13,80.24 15.13,92.8 v2(14.54,93.39)
  BOTTOM w0.254: v2(14.54,93.39) 15.02,93.39 15.33,93.69 U545.7
GPIO3_16: length 76.7
  TOP w0.137: v2(14.53,90.62) 14.53,91.04 14.54,91.05 J67.17 ; U14.AE3 v2(55.82,55)
  L3_INT_1 w0.107: v2(14.53,90.62) 14.82,90.33 14.82,87.89 14.21,87.28 14.21,74.7 15.33,73.57 15.33,66.56 18.67,63.22 29.91,63.22 29.91,63.21 29.98,63.21 30.81,62.38 31.62,62.38 34.99,59.01 39.97,59.01 40.34,58.64 40.88,58.64 41.9,57.62 44.66,57.62 46.02,56.27 47.63,56.27 48.7,57.35 50.72,57.35 51.18,56.89 51.2,56.89 51.21,56.88 53.4,56.88 54.06,56.21 54.99,56.21 55.82,55.38 v2(55.82,55)
  BOTTOM w0.137: U545.6 16.47,93.19 14.49,91.22 14.49,91.07 14.53,91.04 v2(14.53,90.62)
GPIO3_17: length 75.9
  TOP w0.137: U14.AE4 v2(55.82,54.2) ; v2(13.97,88.12) 13.97,88.81 J67.19
  L3_INT_1 w0.107: v2(55.82,54.2) 55.72,54.2 55.31,54.6 53.78,54.6 52.16,56.22 47.9,56.22 47.72,56.04 45.92,56.04 44.64,57.32 40.69,57.32 39.24,58.77 34.89,58.77 31.52,62.14 30.65,62.14 29.81,62.98 18.57,62.98 15.09,66.47 15.09,73.38 13.97,74.5 v2(13.97,88.12)
  BOTTOM w0.137: v2(13.97,88.12) 15.33,89.48 15.33,91.56 16.47,92.69 U545.5
GPIO3_21: length 100.5
  TOP w0.137: v2(42.89,56.29) 45.35,58.75 45.35,60.73 46.51,61.9 47.18,61.9 52.59,67.3 v2(52.59,71.9) ; U548.4 88.15,112.63 88.28,112.75 v2(88.28,113.17) ; U14.AG4 v2(54.22,54.2)
  L3_INT_1 w0.107: v2(54.22,54.2) 53.8,54.2 52.01,55.98 48,55.98 47.82,55.8 45.65,55.8 45.16,56.29 v2(42.89,56.29) ; v2(52.59,71.9) 52.59,81.6 54.05,83.06 54.05,85.35 58.96,90.26 58.96,92.04 62.25,95.33 62.25,97.92 64.84,100.51 64.84,106.59 69.02,110.76 69.56,110.76 72.6,113.81 87.64,113.81 v2(88.28,113.17)
GPIO_FUSE_PROG: length 58.6
  TOP w0.137: U14.AE1 56.22,56.71 v2(56.21,56.72) ; U549.6 100.9,63.82 100.9,63.82 v2(100.47,63.82)
  L3_INT_1 w0.107: v2(94.72,64.91) 95.28,64.35 97.2,64.35 97.48,64.06 98.57,64.06 98.81,63.82 v2(100.47,63.82) ; v2(93.02,57.99) 92.73,57.7 91.66,57.7 91.21,58.15 90.07,58.15 88.76,59.46 85.37,59.46 85.16,59.25 84.24,59.25 83.67,59.82 80.89,59.82 79.56,58.49 77.85,58.49 74.7,55.35 72.72,55.35 72.38,55.01 72.06,55.01 70.86,56.22 62.35,56.22 61.44,57.12 56.62,57.12 v2(56.21,56.72)
  L4_INT_2 w0.107: v2(94.72,64.91) 93.84,64.91 93.39,64.47 93.39,58.35 v2(93.02,57.99)
  BOTTOM w0.137: v2(94.72,64.91) 94.13,65.5 R412.1
GVDD: length 77.3
  TOP w0.254: U561.31 75.54,75.26 75.88,74.92 v4(76.39,74.92)
  TOP w0.381: v2(44.24,24.14) 44.75,24.66 C282.1 ; v1(73.42,35) 73.02,35.4 U14.D27 ; U14.U27 62.62,35.4 v1(62.23,35) ; U14.R22 64.22,39.4 v1(63.83,39) ; v1(67.02,39) 66.62,39.4 U14.M22 ; v1(59.03,35) 59.42,35.4 U14.AA27 ; U14.F27 v1(71.82,35) ; U14.AE27 56.22,35.4 v1(55.83,35) ; v1(77.32,6.9) 77.32,6.91 U16.R1 ; U14.AG27 54.62,35.4 v1(54.23,35) ; v1(75.02,35) 74.62,35.4 U14.B27 ; R140.1 v2(62.82,30.22) ; U14.K27 68.22,35.4 v2(68.62,35) ; U14.AH27 53.82,35.4 v1(53.43,35) ; v1(62.23,39) 62.62,39.4 U14.U22 ; R142.1 v7(52.06,3.07) ; U14.AC27 57.82,35.4 v1(57.43,35) ; v1(65.84,6.9) 65.84,6.91 U565.R1 ; U14.M27 66.62,35.4 v2(67.02,35) ; U14.P27 65.02,35.4 v1(65.42,35) ; U14.L22 v1(67.82,39) ; v1(61.43,39) 61.82,39.4 U14.V22 ; U14.H27 69.82,35.4 v1(70.22,35) ; C284.1 v2(45.63,28.52) ; U14.W27 61.02,35.4 v1(60.63,35) ; U14.P22 65.02,39.4 v1(65.42,39) ; v1(63.03,39) 63.42,39.4 U14.T22 ; v1(66.22,39) 65.82,39.4 U14.N22
  TOP w0.432: U17.B9 v1(62,17.71) ; U15.G7 v1(93.82,13.31) ; U565.F8 v1(72.68,14.51) ; U17.D1 v1(54.8,16.11) ; U565.F2 v1(67.08,14.51) ; v1(49.32,11.71) v1(50.12,11.71) ; U17.F8 v1(61.2,14.51) ; U16.D9 v1(84.96,16.11) ; v1(88.68,6.9) 88.68,6.91 U15.R1 ; v1(77.4,11.33) 77.77,11.71 U16.J1 U16.J2 ; U17.A9 61.99,18.5 v1(62.01,18.5) ; U16.A1 v2(77.76,18.51) ; U17.C1 v1(54.8,16.91) ; U17.G1 v1(54.8,13.71) ; U17.G9 v1(62,13.71) ; U565.B9 v1(73.48,17.71) ; U15.F8 v1(95.64,14.51) ; U16.F8 v1(84.16,14.51) ; v1(65.91,11.33) 66.29,11.71 U565.J1 U565.J2 ; U17.A1 v1(54.8,18.51) ; U16.B9 v1(84.96,17.71) ; U16.G9 v1(84.96,13.71) ; U565.A9 v1(73.48,18.51) ; U16.F2 v1(78.56,14.51) ; U15.J2 v1(89.64,11.71) ; U16.G7 v1(83.36,13.71) ; U18.D9 v1(50.52,16.11) ; U565.G7 v1(71.88,13.71) ; U15.G9 v1(96.66,13.31) ; U565.G1 v1(66.28,13.71) ; U16.J8 v1(84.56,11.71) ; U16.G1 v1(77.76,13.71) ; U18.C1 v1(43.32,16.91) ; U15.D9 v1(96.66,15.71) ; U18.F8 v1(49.72,14.51) ; U565.D9 v1(73.48,16.11) ; v1(54.39,6.93) 54.42,6.91 U17.R1 ; U15.A9 v1(96.44,18.51) ; U565.B3 v1(67.88,17.71) ; U16.D1 v1(77.76,16.11) ; U565.C1 v2(66.28,16.91) ; U18.D1 v1(43.32,16.11) ; U15.D1 v1(89.24,16.11) ; U17.B3 v1(56.4,17.71) ; U18.A9 v1(50.52,18.51) ; U16.A9 v1(84.96,18.51) ; U15.G1 v1(89.24,13.71) ; U18.A1 v1(43.32,18.51) ; U565.J8 v1(73.08,11.71) ; U18.G9 v1(50.52,13.71) ; U18.B9 v1(50.52,17.71) ; U565.G9 v1(73.48,13.71) ; U15.C1 v2(89.24,16.91) ; U565.D1 v1(66.28,16.11) ; U17.D9 v1(62,16.11) ; U16.C1 v2(77.76,16.91) ; U18.B3 v1(44.92,17.71) ; U15.B9 v1(96.66,17.31) ; v1(91.83,17.31) U15.B3 ; U565.A1 v1(66.28,18.51) ; v1(79.36,17.71) U16.B3 ; U15.A1 v1(89.24,18.51) ; U18.G7 v1(48.92,13.71) ; U15.F2 v1(90.04,14.51) ; U17.G7 v1(59.42,13.47) ; U17.F2 v1(55.6,14.51)
  BOTTOM w0.381: C303.1 C315.1 65.72,38.91 65.74,38.93 C314.1 ; v2(66.28,16.91) 66.25,16.94 65.51,16.94 C1572.1 ; C1570.1 73.13,11.66 v1(73.08,11.71) ; R558.1 v4(103.49,16.02) ; C521.1 51.15,13.71 v1(50.52,13.71) ; v2(77.76,16.91) 77.7,16.84 C1410.1 ; v1(89.64,10.11) 89.19,10.56 C1387.1 ; C1379.1 50.13,6.11 v1(50.12,6.11) ; v1(43.72,6.91) 43.71,6.9 C1365.1 ; v1(89.64,11.71) 89.63,11.7 C1392.1 ; C1403.1 88.29,16.91 v2(89.24,16.91) ; C306.1 67.04,34.98 v2(67.02,35) ; C1417.1 84.61,11.66 v1(84.56,11.71) ; C1396.1 v1(61.6,10.11) ; v1(96.04,11.71) 96.05,11.71 C1393.1 ; v2(45.63,28.52) C284.1
  BOTTOM w0.508: v2(70.85,15.33) 70.2,15.33 R82.1 ; C431.1 44.33,4.71 v7(43.7,4.08)
  vias: v1(41.02,10.3) v1(41.51,13.61) v1(43.72,13.31) v1(43.72,11.71) v1(43.72,10.11) v1(44.52,14.11) v1(44.52,11.71) v1(50.12,10.11) v1(51.93,10.69) v1(55.2,11.71) v1(55.2,10.11) v1(56,11.71) v1(60.8,11.71) v1(61.6,11.71) v1(61.6,6.11) v1(66.68,10.11) v1(71.77,19.12) v1(73.08,10.11) v1(73.08,6.11) v1(78.16,10.11) v1(84.56,10.11) v1(84.56,6.11) v1(86.45,9.57) v1(95.24,11.71) v1(96.04,10.11) v1(96.04,6.11) v2(38.85,23.39) v2(39.23,25.93) v2(39.48,23.39) v2(39.86,25.93) v2(40.12,23.39) v2(40.68,26.06) v2(40.68,25.3) v2(40.7,24.46) v2(40.73,23.64) v2(40.73,22.88) v2(41.31,26.05) v2(41.32,25.29) v2(41.34,24.46) v2(41.37,23.64) v2(41.37,22.88) v4(35.67,11.83) v4(35.68,15.37) v4(35.7,13) v4(35.7,10.66) v4(35.74,8.35) v4(35.74,6) v4(35.8,14.16) v4(35.79,7.12) v4(80.85,70.33) v4(81.53,72.35) v4(81.57,71.13) v4(82.21,72.19) v4(82.62,70.9) v4(82.75,72.64) v4(82.9,69.91) v4(97.04,29.05) v4(97.11,27.7) v4(98.08,29.07) v4(98.08,27.73) v4(99.07,29.13) v4(99.07,27.73) v7(53.23,14.11) v7(64.63,8.27) v7(64.83,14.11) v7(76.15,8.27) v7(76.29,14.22) v7(87.67,14.09)
I2C1_CH0_SCL: length 175.2
  TOP w0.137: U558.5 130.44,55.95 128.84,55.95 127.62,57.18 110.3,57.18 109.6,57.88 103.37,57.88 102.59,58.66 102.59,60.08 v2(102.19,60.47) 102.02,60.64 U28.8 ; U525.5 v2(89.52,84.46) 88.8,83.74 86.24,83.74 83.08,86.9 69.08,86.9 68.51,86.33 68.51,84.48 68.14,84.11 v4(68.14,83.6) 68.14,83.15 68.1,83.11 U561.55 ; U524.6 v2(103.48,81.14)
  L3_INT_1 w0.107: v2(103.48,81.14) 103.27,81.14 101.94,79.81 95.91,79.81 92.19,83.53 90.36,83.53 89.52,84.36 v2(89.52,84.46) ; v2(18.78,72.66) 22.08,72.66 23.8,70.94 28.63,70.94 30.07,69.5 30.07,69.34 32.18,67.23 34.27,67.23 34.59,66.91 56.9,66.91 59.29,64.52 62.41,64.52 64.03,66.14 65.92,66.14 66.33,66.55 v2(66.96,66.55)
  L4_INT_2 w0.107: v2(102.19,60.47) 102.73,61.02 102.73,61.5 103.93,62.7 103.93,65.06 102.98,66.01 102.98,75.6 103.15,75.77 103.15,80.04 103.32,80.21 103.32,80.98 v2(103.48,81.14) ; v4(68.14,83.6) 67.84,83.29 67.48,83.29 67.2,83.02 67.2,72.18 67.38,71.99 67.38,68.51 67.8,68.1 67.8,67.3 67.34,66.84 67.24,66.84 v2(66.96,66.55)
  BOTTOM w0.137: v2(89.52,84.46) 89.59,84.52 R750.2 ; v2(18.78,72.66) U523.1
I2C1_CH0_SDA: length 175
  TOP w0.137: U561.56 67.6,82.17 67.66,82.22 67.66,83.66 v4(67.49,83.82) 67.49,84.3 68.12,84.93 68.12,86.49 68.92,87.29 83.24,87.29 86.4,84.13 88.5,84.13 v2(88.87,84.5) U525.4 ; U524.5 v2(103.56,79.87) ; U28.7 101.72,59.37 v2(102.16,59.81) 102.16,58.54 103.21,57.49 109.44,57.49 110.14,56.79 127.46,56.79 128.68,55.56 130.44,55.56 U558.4
  L3_INT_1 w0.107: v2(88.87,84.5) 90.1,83.27 90.27,83.11 92.1,83.11 95.76,79.45 102.09,79.45 102.52,79.87 v2(103.56,79.87) ; v2(18.78,76.47) 23.95,71.3 28.78,71.3 30.43,69.65 30.43,69.49 32.33,67.59 34.42,67.59 34.74,67.27 57.05,67.27 59.44,64.88 62.26,64.88 63.99,66.61 65.72,66.61 66.16,67.05 v2(66.57,67.05)
  L4_INT_2 w0.107: v2(66.57,67.05) 66.57,68.73 67.02,69.18 67.02,71.84 66.84,72.03 66.84,83.17 v4(67.49,83.82) ; v2(103.56,79.87) 103.54,79.85 103.54,79.73 103.51,79.71 103.51,75.62 103.34,75.45 103.34,66.16 104.29,65.21 104.29,62.55 103.09,61.35 103.09,60.87 102.69,60.46 102.69,60.34 v2(102.16,59.81)
  BOTTOM w0.137: v2(88.87,84.5) 88.71,84.67 R751.2 ; U523.4 18.61,76.47 18.62,76.47 v2(18.78,76.47)
I2C1_M2CARD1_SCL: length 116.2
  TOP w0.137: U525.7 v2(90.82,84.38)
  L3_INT_1 w0.107: v2(38.78,65.45) 43.21,65.45 43.88,66.12 55.86,66.12 59.79,62.19 59.79,60.45 60.06,60.19 61.66,60.19 62.44,60.96 68.08,60.96 70.21,58.83 72.76,58.83 73.14,59.21 73.27,59.21 77.13,63.07 77.15,63.07 77.73,63.65 82.94,63.65 83.13,63.84 v2(83.85,63.84)
  L4_INT_2 w0.107: v2(36.98,51.15) 37.96,52.14 37.96,64.13 38.39,64.55 38.39,64.92 38.78,65.31 v2(38.78,65.45) ; v2(83.85,63.84) 83.85,64.25 83.86,64.26 83.86,64.4 85.58,66.13 85.58,70.46 90.79,75.66 90.79,84.2 90.72,84.28 v2(90.82,84.38)
  BOTTOM w0.137: J46.60 18.88,48.07 18.94,48.12 18.94,50.66 20.53,52.25 35.88,52.25 v2(36.98,51.15) ; R756.2 91.44,85 v2(90.82,84.38)
I2C1_M2CARD1_SDA: length 116
  TOP w0.137: U525.6 v2(90.17,84.31)
  L3_INT_1 w0.107: v2(38.88,64.54) 38.88,64.95 39.02,65.09 43.36,65.09 44.03,65.76 55.71,65.76 59.43,62.04 59.43,60.3 59.91,59.82 61.81,59.82 62.42,60.43 68.1,60.43 70.06,58.47 72.91,58.47 73.29,58.85 73.42,58.85 77.28,62.71 77.3,62.71 77.6,63.01 83.02,63.01 v2(83.31,63.3)
  L4_INT_2 w0.107: v2(37.54,50.46) 38.32,51.24 38.32,63.98 v2(38.88,64.54) ; v2(83.31,63.3) 83.31,64.36 85.22,66.28 85.22,70.61 90.43,75.81 90.43,84.05 v2(90.17,84.31)
  BOTTOM w0.137: v2(90.17,84.31) 90.4,84.53 90.4,84.56 90.47,84.63 R757.2 ; v2(37.54,50.46) 37.07,50.46 35.72,51.81 20.64,51.81 19.33,50.5 19.33,48.12 19.38,48.07 J46.58
I2C1_M2CARD2_SCL: length 134
  TOP w0.137: v2(30.14,36.07) J52.60 ; U525.10 v2(90.82,93.1)
  L3_INT_1 w0.107: v2(39.03,44.06) 39.03,42.07 38.66,41.71 27.81,41.71 27.77,41.67 27.71,41.67 27.46,41.42 27.46,41.36 27.4,41.3 27.4,40.25 30.14,37.52 v2(30.14,36.07) ; v2(40.67,64.58) 40.88,64.37 43.4,64.37 44.15,63.62 47.63,63.62 47.63,63.62 48.37,63.62 48.71,63.27 49.73,63.27 50.35,62.65 52.13,62.65 52.38,62.91 58.13,62.91 59.12,61.91 59.12,60.17 59.88,59.41 63.66,59.41 64.91,58.16 73.04,58.16 73.42,58.54 73.55,58.54 77.41,62.4 77.47,62.4 77.48,62.42 v2(85.36,62.42)
  L4_INT_2 w0.107: v2(90.82,93.1) 91.29,93.57 92.47,93.57 94.53,91.51 94.53,78.07 86.71,70.25 86.71,66.36 85.36,65.02 v2(85.36,62.42) ; v2(40.67,64.58) 40.51,64.58 40.44,64.51 39.72,64.51 38.85,63.64 38.85,49.76 39.65,48.96 39.65,44.7 39.03,44.08 v2(39.03,44.06)
  BOTTOM w0.137: v2(90.82,93.1) 90.82,92.38 R754.2
I2C1_M2CARD2_SDA: length 132.8
  TOP w0.137: U525.9 v2(91.47,93.12) ; J52.58 29.64,36.06 29.65,36.07 v2(29.65,36.49)
  L3_INT_1 w0.107: v2(40.37,63.93) 40.77,63.93 40.84,64.01 43.25,64.01 44,63.26 47.48,63.26 47.48,63.26 48.22,63.26 48.56,62.91 49.58,62.91 50.2,62.29 52.28,62.29 52.53,62.54 57.98,62.54 58.76,61.76 58.76,60.02 59.73,59.05 63.51,59.05 64.76,57.8 73.19,57.8 73.57,58.18 73.7,58.18 77.56,62.04 84.45,62.04 84.51,61.98 84.65,61.98 v2(84.94,61.69) ; v2(38.62,42.69) 38.62,42.18 38.51,42.07 38.37,42.07 38.37,42.07 27.66,42.07 27.62,42.03 27.56,42.03 27.1,41.57 27.1,41.51 27.04,41.45 27.04,40.1 29.65,37.5 v2(29.65,36.49)
  L4_INT_2 w0.107: v2(91.47,93.12) 91.57,93.21 92.32,93.21 94.17,91.36 94.17,78.22 85.82,69.87 85.82,66.03 84.94,65.16 84.94,63.68 84.94,63.68 v2(84.94,61.69) ; v2(40.37,63.93) 40.15,64.15 39.86,64.15 39.21,63.49 39.21,49.91 40.01,49.11 40.01,44.42 38.62,43.03 v2(38.62,42.69)
  BOTTOM w0.137: R755.2 91.47,92.43 v2(91.47,93.12)
I2C1_SCL: length 101.5
  TOP w0.137: U538.3 108.04,64.47 107.63,64.88 v2(107.63,65.56) ; U14.N1 65.82,56.57 66.02,56.76 66.02,64.16 v2(65.16,65.02) ; U525.14 v2(88.22,93.04)
  L3_INT_1 w0.107: v2(88.22,93.04) 90.15,91.12 91.74,91.12 96.73,86.14 101.67,86.14 103.72,84.09 104.31,84.09 105,83.4 105,79.61 v2(104.55,79.16) ; v2(107.63,65.56) 106.01,67.18 106.01,68.22 105.32,68.91 100.26,68.91 99.65,69.52 96.9,69.52 95.37,68 87.14,68 85.79,66.64 75.38,66.64 73.78,65.04 68.46,65.04 68.18,65.31 65.51,65.31 65.22,65.02 v2(65.16,65.02)
  L4_INT_2 w0.107: v2(104.55,79.16) 105.04,79.16 105.74,78.46 105.74,77.9 108.55,75.09 108.55,66.55 107.92,65.92 107.92,65.85 v2(107.63,65.56)
  BOTTOM w0.137: R749.2 88.38,92.89 v2(88.22,93.04)
I2C1_SDA: length 102
  TOP w0.137: v2(65.9,64.9) 66.41,64.39 66.41,56.78 66.62,56.57 U14.M1 ; U538.6 106.13,64.47 106.47,64.81 v2(106.47,65.58) ; U525.15 v2(87.57,93.05)
  L3_INT_1 w0.107: v2(65.9,64.9) 65.88,64.92 65.88,64.94 65.89,64.95 68.03,64.95 68.31,64.68 73.93,64.68 75.53,66.28 85.94,66.28 87.29,67.63 95.52,67.63 97.05,69.16 99.5,69.16 100.11,68.55 105.17,68.55 105.65,68.07 105.65,67.03 106.47,66.21 v2(106.47,65.58) ; v2(104.6,78.53) 105.36,79.29 105.36,83.76 102.62,86.5 97.24,86.5 91.92,91.81 90.26,91.81 88.57,93.5 88.02,93.5 v2(87.57,93.05)
  L4_INT_2 w0.107: v2(104.6,78.53) 105.17,78.53 105.38,78.31 105.38,77.72 108.19,74.92 108.19,67.13 106.93,65.87 106.76,65.87 v2(106.47,65.58)
  BOTTOM w0.137: R748.2 87.49,92.97 v2(87.57,93.05)
I2C1_UBUS_SCL: length 15.3
  TOP w0.137: v2(89.42,93.24) 89.52,93.13 U525.12
  L3_INT_1 w0.107: v2(89.23,103.54) 89.19,103.54 89.19,103.57 88.96,103.34 88.96,94.1 89.42,93.64 v2(89.42,93.24)
  BOTTOM w0.137: J57.5 92.06,104.44 R752.2 89.32,103.54 v2(89.23,103.54)
I2C1_UBUS_SDA: length 12.2
  TOP w0.137: U525.11 v2(90.17,93.36)
  L3_INT_1 w0.107: v2(89.58,100.95) 89.58,94.45 90.17,93.85 v2(90.17,93.36)
  BOTTOM w0.137: v2(89.58,100.95) 90.17,101.55 R753.2 91.74,101.55 J57.6
I2C3_SCL: length 11.9
  TOP w0.137: v2(107.62,76.92) 107.2,76.92 107.16,76.88 107.12,76.88 107.04,76.8 105.12,76.8 104.32,77.6 104.32,77.6 104.07,77.84 U554.4
  BOTTOM w0.137: v2(107.62,76.92) 107.62,75.54 107.94,75.23 107.94,73.43 108.04,73.32 108.9,73.32 109.49,72.73 R854.2 J64.3
I2C3_SDA: length 11.8
  TOP w0.137: U554.5 104.26,78.24 105.01,77.49 v2(106.74,77.49)
  BOTTOM w0.137: v2(106.74,77.49) 106.74,77.07 106.79,77.02 106.79,75.63 105.99,74.83 105.99,74.8 105.98,74.79 105.98,73.43 105.87,73.32 104.95,73.32 R853.2 104.28,72.08 104.41,71.96 J64.1
I2C3_USB2_SEL: length 3
  TOP w0.137: v2(101.03,77.13) 101.34,77.44 U554.10
  BOTTOM w0.137: U555.2 100.31,76.74 100.7,77.13 v2(101.03,77.13)
I2C3_USB2_SEL_IO: length 71
  TOP w0.137: v2(98.71,73.67) 98.71,74.19 v2(99.02,74.49) R885.1 ; U14.AD1 57.02,56.68 55.92,57.78 54.45,57.78 53.32,58.92 53.32,60.23 53.95,60.86 53.95,65.02 53.81,65.16 v2(53.81,71.82)
  L3_INT_1 w0.107: v2(98.71,73.67) 95.36,73.67 93.91,72.22 82.95,72.22 82.3,71.58 80.56,71.58 79.36,70.37 65.33,70.37 64.12,69.17 62.63,69.17 62.44,69.36 59.35,69.36 56.88,71.82 v2(53.81,71.82)
  BOTTOM w0.137: v2(99.02,74.49) 99.53,74.49 100.31,73.71 U555.7
I2C4_SCL: length 64.1
  TOP w0.137: v3(67.04,55.01) U14.M3
  L3_INT_1 w0.107: J63.3 108.31,73.25 108.31,70.27 107.45,69.4 103.18,69.4 102.51,70.07 96.85,70.07 95.19,68.41 87.12,68.41 85.66,66.95 75.25,66.95 74.59,66.29 67.85,66.29 v2(67.38,65.82)
  BOTTOM w0.137: v3(67.04,55.01) 67.04,56.44 69.67,59.07 69.67,63.17 69.1,63.74 69.1,64.21 68.56,64.75 68.56,64.94 68.8,65.18 68.8,65.37 68.6,65.56 68.41,65.56 68.17,65.33 67.98,65.33 67.79,65.52 67.68,65.52 v2(67.38,65.82) ; R852.2 J63.3
I2C4_SDA: length 65.3
  TOP w0.137: v3(66.22,54.99) U14.N3
  L3_INT_1 w0.107: J63.1 105.7,73.14 106.31,73.14 107.95,71.5 107.95,70.67 107.05,69.76 103.33,69.76 102.66,70.43 96.7,70.43 95.04,68.77 86.97,68.77 85.51,67.31 75.1,67.31 74.44,66.65 67.64,66.65 67.12,66.14 67.12,66.14 67.08,66.09 66.8,66.09 v2(66.51,65.8)
  BOTTOM w0.137: v3(66.22,54.99) 66.62,55.39 66.62,56.58 69.28,59.23 69.28,63.01 68.71,63.58 68.71,64.05 67.63,65.13 67.19,65.13 v2(66.51,65.8) ; R851.2 J63.1
I2C_ADDR_A0: length 3.5
  TOP w0.137: U50.10 23.53,67.85 22.54,68.84 22.54,69.11 R277.2
IFC_AD0: length 68.4
  TOP w0.137: U14.B8 74.98,50.96 75.69,50.96 78.14,53.4 v2(83.58,53.4)
  L3_INT_1 w0.107: v2(83.58,53.4) 83.87,53.69 85.44,53.69 85.47,53.71 86.27,53.71 86.29,53.73 86.84,53.73 86.86,53.71 101.61,53.71 101.68,53.64 102.39,53.64 103.67,52.37 105.72,52.37 113.2,44.89 113.2,36.95 113.86,36.28 113.86,22.9 112.71,21.75 v3(112.21,21.75)
  BOTTOM w0.137: U522.J8 v3(112.21,21.75)
IFC_AD1: length 65.5
  TOP w0.137: v2(83.08,52.89) 81.48,52.89 81.09,52.5 80.72,52.5 80.68,52.55 77.82,52.55 75.87,50.6 U14.A8
  L3_INT_1 w0.107: v3(113.08,22.63) 113.4,22.95 113.4,24.81 113.03,25.18 113.03,30.96 112.68,31.31 112.68,36.27 112.16,36.78 112.16,45.32 105.88,51.6 103.03,51.6 102.62,52.01 102.62,52.37 101.51,53.48 86.76,53.48 86.74,53.5 86.38,53.5 86.36,53.48 85.56,53.48 84.97,52.89 v2(83.08,52.89)
  BOTTOM w0.137: U522.K7 v3(113.08,22.63)
IFC_AD2: length 65.7
  TOP w0.137: v2(83.55,52.35) 81.57,52.35 81.39,52.17 79.07,52.17 77.63,50.74 76.37,50.74 75.86,50.23 75.06,50.23 U14.B9
  L3_INT_1 w0.107: v3(111.49,21.83) 111.49,22.31 112.1,22.93 112.35,22.93 112.63,23.21 112.63,30.73 111.52,31.84 111.52,39.77 109.35,41.93 109.35,45.61 108.85,46.12 107.73,46.12 104.86,48.99 104.86,49.14 104.98,49.26 104.98,49.41 104.83,49.56 104.68,49.56 104.56,49.44 104.41,49.44 104.17,49.68 104.17,50.09 103.8,50.46 102.91,50.46 102.52,50.84 102.52,51.07 101.24,52.35 v2(83.55,52.35)
  BOTTOM w0.137: U522.J7 v3(111.49,21.83)
IFC_AD3: length 65
  TOP w0.137: U14.A9 75.8,49.8 76.48,50.47 77.9,50.47 79.3,51.87 v2(82.56,51.87)
  L3_INT_1 w0.107: v2(82.56,51.87) 96.36,51.87 96.56,52.06 100.13,52.06 101.1,51.09 101.56,51.09 104.21,48.45 104.21,48.3 103.89,47.98 103.89,47.83 104.04,47.68 104.2,47.68 104.51,48 104.66,48 105.4,47.26 105.4,46.85 105.66,46.59 105.81,46.59 106.11,46.9 106.26,46.9 106.41,46.74 106.41,46.59 106.11,46.29 106.11,46.14 106.26,45.99 106.41,45.99 106.71,46.29 106.86,46.29 107.01,46.14 107.01,45.99 106.71,45.69 106.71,45.54 107.63,44.62 107.96,44.62 108.32,44.26 108.32,43.46 108.42,43.36 108.7,43.36 108.81,43.25 108.81,43.04 108.7,42.93 108.42,42.93 108.32,42.82 108.32,42.61 108.42,42.5 108.7,42.5 108.81,42.4 108.81,42.18 108.7,42.08 108.42,42.08 108.32,41.97 108.32,41.55 110.5,39.36 110.5,34.66 110.93,34.22 110.93,31.94 112.27,30.61 v3(112.27,23.35)
  BOTTOM w0.137: U522.K6 v3(112.27,23.35)
IFC_AD4: length 65.1
  TOP w0.137: v2(83.51,51.44) 81.73,51.44 81.02,50.73 78.6,50.73 78,50.12 76.55,50.12 U14.A10
  L3_INT_1 w0.107: v2(83.51,51.44) 95.2,51.44 95.78,50.86 101.41,50.86 102.5,49.78 102.5,48.3 103.64,47.16 103.64,46.35 103.81,46.18 103.96,46.18 104.31,46.53 104.46,46.53 104.61,46.38 104.61,46.23 104.26,45.88 104.26,45.73 104.41,45.57 104.56,45.57 104.92,45.93 105.07,45.93 105.22,45.78 105.22,45.62 104.87,45.27 104.87,45.12 105.02,44.97 105.17,44.97 105.52,45.32 105.67,45.32 105.82,45.17 105.82,45.02 105.47,44.67 105.47,44.52 105.62,44.37 105.77,44.37 106.12,44.72 106.27,44.72 106.42,44.57 106.42,44.42 106.07,44.07 106.07,43.92 106.37,43.62 107.19,43.62 107.53,43.27 107.53,41.37 109.79,39.11 109.79,35.01 110.28,34.52 110.28,34.5 110.53,34.25 v2(110.53,31.41)
  BOTTOM w0.137: v2(110.53,31.41) 113.85,28.08 113.85,25.01 113.05,24.21 113.05,24.2 U522.K5
IFC_AD5: length 65
  TOP w0.137: v2(84.03,50.74) 83.13,50.74 82.65,50.26 79.41,50.26 78.38,49.23 76.25,49.23 75.65,48.63 75.06,48.63 U14.B11
  L3_INT_1 w0.107: v2(84.03,50.74) 84.5,51.2 95.05,51.2 96.61,49.65 99.53,49.65 102.91,46.27 103,46.27 103.91,45.37 103.91,45.22 103.56,44.87 103.56,44.72 103.71,44.57 103.86,44.57 104.21,44.91 104.36,44.91 104.51,44.76 104.51,44.61 104.16,44.26 104.16,44.11 104.31,43.96 104.46,43.96 104.81,44.31 104.96,44.31 105.11,44.16 105.11,44.01 104.76,43.66 104.76,43.51 104.92,43.36 105.07,43.36 105.41,43.71 105.57,43.71 105.72,43.56 105.72,43.41 105.37,43.06 105.37,42.91 105.52,42.76 105.67,42.76 106.02,43.1 106.17,43.1 106.39,42.89 106.39,41.5 107.44,40.44 107.59,40.44 107.73,40.58 107.88,40.58 108.03,40.43 108.03,40.28 107.89,40.14 107.89,39.99 108.04,39.84 108.19,39.84 108.33,39.98 108.48,39.98 108.63,39.83 108.63,39.68 108.5,39.54 108.5,39.39 108.65,39.24 108.8,39.24 108.94,39.37 109.09,39.37 109.24,39.22 109.24,39.07 109.1,38.93 109.1,38.78 109.39,38.49 109.39,35.08 110.05,34.43 110.05,34.09 110.04,34.08 110.04,32.35 v2(109.69,32)
  BOTTOM w0.137: v2(109.69,32) 109.69,31.57 111.87,29.39 111.87,28.74 112.01,28.61 112.4,28.61 112.54,28.47 112.54,28.2 112.4,28.06 112.01,28.06 111.87,27.92 111.87,26.53 112.27,26.14 112.27,24.96 U522.K4
